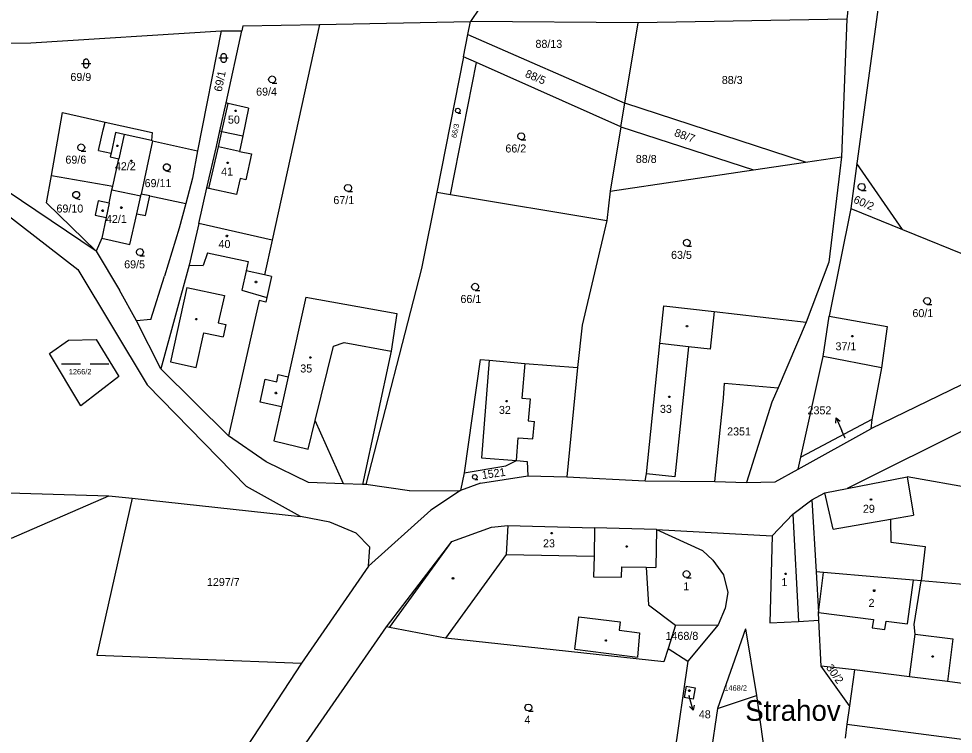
# Model space of a CAD drawing. Extents: x -852001 to -842497, y -1063614 to -1052182.
# Drawn here: x -850781 to -850582.4, y -1053481.6 to -1053329.6 of the extents above; entities that cross this region are included whole.
import ezdxf

# ---------------------------------------------------------------- set-up
doc = ezdxf.new("R2010")
doc.units = 0
for name, color, linetype in [('Default', 7, 'Continuous'), ('KN_HRANICE', 7, 'Continuous'), ('KN_KULTURY', 7, 'Continuous'), ('KN_PARCELY', 7, 'Continuous'), ('KN_SLUCKY', 7, 'Continuous')]:
    doc.layers.add(name, color=color, linetype=linetype)

# ---------------------------------------------------------------- blocks, each defined once
blk = doc.blocks.new('304')
at = {"layer": 'Default'}
blk.add_lwpolyline([(0, 0), (-0.38, 0.1), (-0.65, 0.37), (-0.75, 0.74), (-0.65, 1.11), (-0.38, 1.38), (-0.01, 1.48), (0.36, 1.38), (0.63, 1.11), (0.73, 0.73), (0.63, 0.35), (0.36, 0.08), (-0.02, -0.02), (0.98, -0.02)], dxfattribs=at)
blk = doc.blocks.new('316')
at = {"layer": 'Default'}
for points in [[(-1, 1), (0.27, 1), (1, 1)], [(-0.5, 1.5), (-0.4, 1.79), (-0.15, 1.97), (0.16, 1.97), (0.41, 1.79), (0.51, 1.5), (0.51, 0.5), (0.41, 0.21), (0.16, 0.03), (-0.15, 0.03), (-0.4, 0.21), (-0.5, 0.5), (-0.5, 1.5)]]:
    blk.add_lwpolyline(points, dxfattribs=at)
blk = doc.blocks.new('803')
at = {"layer": 'Default'}
for p, q in [((-7.5, 0), (-1.5, 0)), ((1.5, 0), (7.5, 0))]:
    blk.add_line(p, q, dxfattribs=at)
blk = doc.blocks.new('10292')
at = {"layer": 'Default'}
blk.add_line((0, 3), (0, 0), dxfattribs=at)
blk.add_lwpolyline([(-0.5, 2), (0, 3), (0.5, 2)], dxfattribs=at)
blk = doc.blocks.new('402')
at = {"layer": 'Default'}
blk.add_lwpolyline([(0.09, 0.15), (0.18, 0), (0.09, -0.15), (-0.09, -0.15), (-0.18, 0), (-0.09, 0.15), (0.09, 0.15)], dxfattribs=at)

msp = doc.modelspace()

# ---------------------------------------------------------------- linework, layer by layer
at = {"layer": 'KN_HRANICE'}
for p, q in [((-850601.94, -1053301.5), (-850605.07, -1053329.74)), ((-850595.22, -1053304.04), (-850602.92, -1053360.4)), ((-850683.07, -1053327.37), (-850685.02, -1053330.25)), ((-850717.05, -1053330.88), (-850685.02, -1053330.25)), ((-850685.56, -1053333), (-850685.02, -1053330.25)), ((-850649.35, -1053330.52), (-850685.02, -1053330.25)), ((-850652.19, -1053347.57), (-850649.35, -1053330.52)), ((-850605.07, -1053329.74), (-850649.35, -1053330.52)), ((-850605.07, -1053329.74), (-850606.19, -1053358.98)), ((-850778.4, -1053334.78), (-850737.94, -1053332.24)), ((-850737.94, -1053332.24), (-850742.99, -1053357.7)), ((-850737.94, -1053332.24), (-850733.55, -1053332.18)), ((-850736.86, -1053347.53), (-850733.55, -1053332.18)), ((-850733.34, -1053331.11), (-850733.55, -1053332.18)), ((-850733.34, -1053331.11), (-850717.05, -1053330.88)), ((-850717.05, -1053330.88), (-850727.14, -1053376.69)), ((-850686.5, -1053337.71), (-850685.56, -1053333)), ((-850685.56, -1053333), (-850652.19, -1053347.57)), ((-850815.48, -1053335.08), (-850778.4, -1053334.78)), ((-850686.5, -1053337.71), (-850692.17, -1053366.45)), ((-850683.69, -1053338.94), (-850686.5, -1053337.71)), ((-850689.22, -1053366.95), (-850683.69, -1053338.94)), ((-850653.03, -1053352.56), (-850683.69, -1053338.94)), ((-850738.2, -1053353.47), (-850736.86, -1053347.53)), ((-850736.47, -1053347.62), (-850736.86, -1053347.53)), ((-850732.12, -1053348.62), (-850736.47, -1053347.62)), ((-850653.03, -1053352.56), (-850652.19, -1053347.57)), ((-850613.8, -1053360.1), (-850652.19, -1053347.57)), ((-850774.01, -1053362.91), (-850771.62, -1053349.55)), ((-850771.62, -1053349.55), (-850762.61, -1053351.58)), ((-850732.12, -1053348.62), (-850733.38, -1053354.52)), ((-850762.99, -1053353.25), (-850762.61, -1053351.58)), ((-850762.61, -1053351.58), (-850752.61, -1053353.83)), ((-850763.97, -1053357.61), (-850762.99, -1053353.25)), ((-850752.61, -1053353.83), (-850752.76, -1053355.52)), ((-850738.94, -1053356.76), (-850738.2, -1053353.47)), ((-850738.2, -1053353.47), (-850737.81, -1053353.56)), ((-850737.81, -1053353.56), (-850733.38, -1053354.52)), ((-850733.38, -1053354.52), (-850734.08, -1053357.8)), ((-850653.03, -1053352.56), (-850655.32, -1053366.23)), ((-850653.03, -1053352.56), (-850624.89, -1053361.75)), ((-850752.51, -1053355.58), (-850754.95, -1053366.89)), ((-850752.51, -1053355.58), (-850752.76, -1053355.52)), ((-850752.51, -1053355.58), (-850742.99, -1053357.7)), ((-850763.97, -1053357.61), (-850761.34, -1053358.18)), ((-850761.34, -1053358.18), (-850761.52, -1053358.99)), ((-850742.99, -1053357.7), (-850744.07, -1053363.49)), ((-850740.97, -1053365.57), (-850738.94, -1053356.76)), ((-850734.08, -1053357.8), (-850731.54, -1053358.34)), ((-850731.54, -1053358.34), (-850732.71, -1053363.82)), ((-850761.52, -1053358.99), (-850759.68, -1053359.39)), ((-850760.97, -1053365.18), (-850759.68, -1053359.39)), ((-850624.89, -1053361.75), (-850613.8, -1053360.1)), ((-850613.8, -1053360.1), (-850606.19, -1053358.98)), ((-850606.19, -1053358.98), (-850606.54, -1053361.94)), ((-850602.92, -1053360.4), (-850604.22, -1053369.95)), ((-850593.21, -1053374.4), (-850602.92, -1053360.4)), ((-850655.32, -1053366.23), (-850624.89, -1053361.75)), ((-850606.54, -1053361.94), (-850608.91, -1053381.35)), ((-850775.07, -1053368.7), (-850774.01, -1053362.91)), ((-850774.01, -1053362.91), (-850760.97, -1053365.18)), ((-850744.07, -1053363.49), (-850745.43, -1053368.86)), ((-850733.94, -1053363.56), (-850734.66, -1053366.93)), ((-850732.71, -1053363.82), (-850733.94, -1053363.56)), ((-850764.51, -1053379), (-850783.59, -1053366.1)), ((-850761.73, -1053368.82), (-850761.14, -1053365.96)), ((-850761.14, -1053365.96), (-850760.97, -1053365.18)), ((-850761.14, -1053365.96), (-850755.03, -1053367.28)), ((-850742.71, -1053373.12), (-850740.97, -1053365.57)), ((-850740.58, -1053365.66), (-850740.97, -1053365.57)), ((-850734.66, -1053366.93), (-850740.58, -1053365.66)), ((-850655.32, -1053366.23), (-850656.06, -1053372.51)), ((-850764.08, -1053368.33), (-850764.71, -1053371.37)), ((-850761.73, -1053368.82), (-850764.08, -1053368.33)), ((-850755.03, -1053367.28), (-850754.95, -1053366.89)), ((-850753.13, -1053367.26), (-850754.95, -1053366.89)), ((-850754.04, -1053371.43), (-850753.13, -1053367.26)), ((-850753.13, -1053367.26), (-850745.43, -1053368.86)), ((-850692.17, -1053366.45), (-850695.38, -1053382.66)), ((-850692.17, -1053366.45), (-850689.22, -1053366.95)), ((-850689.22, -1053366.95), (-850656.06, -1053372.51)), ((-850775.07, -1053368.7), (-850764.51, -1053379)), ((-850745.43, -1053368.86), (-850746.88, -1053374.1)), ((-850604.22, -1053369.95), (-850608.81, -1053392.78)), ((-850604.22, -1053369.95), (-850593.21, -1053374.4)), ((-850783.8, -1053370.9), (-850768.38, -1053382.92)), ((-850764.71, -1053371.37), (-850762.36, -1053371.85)), ((-850762.36, -1053371.85), (-850763.28, -1053376.26)), ((-850757.36, -1053377.59), (-850755.86, -1053371.06)), ((-850755.86, -1053371.06), (-850754.04, -1053371.43)), ((-850746.88, -1053374.1), (-850750, -1053384.28)), ((-850742.71, -1053373.12), (-850744.73, -1053381.99)), ((-850727.14, -1053376.69), (-850742.71, -1053373.12)), ((-850656.06, -1053372.51), (-850661.28, -1053394.73)), ((-850763.28, -1053376.26), (-850764.51, -1053379)), ((-850763.28, -1053376.26), (-850757.36, -1053377.59)), ((-850593.21, -1053374.4), (-850558.84, -1053388.31)), ((-850727.14, -1053376.69), (-850728.76, -1053384.05)), ((-850764.51, -1053379), (-850759.56, -1053387.26)), ((-850744.73, -1053381.99), (-850750.73, -1053404.02)), ((-850608.91, -1053381.35), (-850613.67, -1053394.11)), ((-850768.38, -1053382.92), (-850753.68, -1053407.41)), ((-850752.92, -1053393.49), (-850750, -1053384.28)), ((-850727.29, -1053384.37), (-850728.76, -1053384.05)), ((-850695.38, -1053382.66), (-850707.19, -1053428.56)), ((-850727.29, -1053384.37), (-850728.26, -1053388.82)), ((-850755.92, -1053393.81), (-850759.56, -1053387.26)), ((-850729.91, -1053389.48), (-850736.41, -1053418.2)), ((-850728.47, -1053389.8), (-850729.91, -1053389.48)), ((-850728.26, -1053388.82), (-850728.47, -1053389.8)), ((-850719.96, -1053388.76), (-850723.72, -1053405.65)), ((-850719.96, -1053388.76), (-850700.61, -1053392.2)), ((-850700.61, -1053392.2), (-850701.86, -1053400.23)), ((-850644.8, -1053398.62), (-850643.92, -1053390.61)), ((-850643.92, -1053390.61), (-850633.21, -1053391.79)), ((-850633.21, -1053391.79), (-850613.67, -1053394.11)), ((-850752.92, -1053393.49), (-850755.92, -1053393.81)), ((-850750.73, -1053404.02), (-850755.92, -1053393.81)), ((-850613.67, -1053394.11), (-850619.67, -1053408.02)), ((-850610.11, -1053401.34), (-850608.81, -1053392.78)), ((-850608.81, -1053392.78), (-850596.48, -1053395.02)), ((-850661.28, -1053394.73), (-850662.28, -1053403.7)), ((-850596.48, -1053395.02), (-850597.72, -1053403.77)), ((-850774.4, -1053400.72), (-850770.36, -1053397.87)), ((-850770.36, -1053397.87), (-850764.52, -1053397.77)), ((-850764.52, -1053397.77), (-850759.66, -1053405.62)), ((-850647.64, -1053426.28), (-850644.8, -1053398.62)), ((-850767.78, -1053411.85), (-850774.4, -1053400.72)), ((-850701.86, -1053400.23), (-850707.94, -1053428.53)), ((-850682.94, -1053401.97), (-850686.34, -1053426.05)), ((-850682.94, -1053401.97), (-850680.99, -1053402.15)), ((-850680.99, -1053402.15), (-850673.43, -1053402.82)), ((-850614.83, -1053422.71), (-850610.11, -1053401.34)), ((-850736.41, -1053418.2), (-850750.73, -1053404.02)), ((-850673.43, -1053402.82), (-850662.28, -1053403.7)), ((-850662.28, -1053403.7), (-850664.55, -1053426.95)), ((-850597.72, -1053403.77), (-850599.75, -1053414.73)), ((-850759.66, -1053405.62), (-850767.78, -1053411.85)), ((-850726.16, -1053406.74), (-850725.82, -1053405.18)), ((-850725.82, -1053405.18), (-850723.72, -1053405.65)), ((-850732.58, -1053428.94), (-850753.68, -1053407.41)), ((-850729.69, -1053411.08), (-850728.61, -1053406.2)), ((-850728.61, -1053406.2), (-850726.16, -1053406.74)), ((-850631.28, -1053410.23), (-850631.01, -1053407.05)), ((-850631.01, -1053407.05), (-850619.67, -1053408.02)), ((-850619.67, -1053408.02), (-850621, -1053411.06)), ((-850580.7, -1053407.38), (-850599.94, -1053416.73)), ((-850725.15, -1053412.09), (-850729.69, -1053411.08)), ((-850725.15, -1053412.09), (-850726.75, -1053419.27)), ((-850633.09, -1053427.94), (-850631.28, -1053410.23)), ((-850621, -1053411.06), (-850626.39, -1053428.15)), ((-850719.44, -1053421.05), (-850717.98, -1053414.96)), ((-850712, -1053428.38), (-850717.98, -1053414.96)), ((-850599.75, -1053414.73), (-850614.83, -1053422.71)), ((-850574.57, -1053414.22), (-850604.96, -1053429.4)), ((-850599.75, -1053414.73), (-850599.94, -1053416.73)), ((-850615.4, -1053425.29), (-850599.94, -1053416.73)), ((-850728.38, -1053423.75), (-850736.41, -1053418.2)), ((-850726.75, -1053419.27), (-850719.44, -1053421.05)), ((-850719.41, -1053428.11), (-850728.38, -1053423.75)), ((-850677.49, -1053424.55), (-850675.24, -1053423.48)), ((-850675.24, -1053423.48), (-850672.94, -1053423.65)), ((-850672.94, -1053423.65), (-850672.81, -1053426.68)), ((-850615.4, -1053425.29), (-850614.83, -1053422.71)), ((-850686.34, -1053426.05), (-850677.49, -1053424.55)), ((-850620.26, -1053427.98), (-850615.4, -1053425.29)), ((-850686.34, -1053426.05), (-850687.09, -1053429.83)), ((-850682.84, -1053428.25), (-850672.81, -1053426.68)), ((-850672.81, -1053426.68), (-850664.55, -1053426.95)), ((-850664.55, -1053426.95), (-850647.86, -1053427.79)), ((-850647.86, -1053427.79), (-850647.64, -1053426.28)), ((-850647.86, -1053427.79), (-850633.09, -1053427.94)), ((-850633.09, -1053427.94), (-850626.39, -1053428.15)), ((-850626.39, -1053428.15), (-850620.26, -1053427.98)), ((-850604.96, -1053429.4), (-850592.25, -1053426.9)), ((-850592.25, -1053426.9), (-850590.88, -1053435.07)), ((-850572.57, -1053430.44), (-850592.25, -1053426.9)), ((-850800.29, -1053429.81), (-850761.82, -1053430.94)), ((-850721.08, -1053435.35), (-850732.58, -1053428.94)), ((-850712, -1053428.38), (-850719.41, -1053428.11)), ((-850707.94, -1053428.53), (-850712, -1053428.38)), ((-850707.19, -1053428.56), (-850707.94, -1053428.53)), ((-850697.93, -1053429.89), (-850707.19, -1053428.56)), ((-850697.93, -1053429.89), (-850687.09, -1053429.83)), ((-850687.09, -1053429.83), (-850693.44, -1053434)), ((-850682.84, -1053428.25), (-850687.09, -1053429.83)), ((-850609.72, -1053430.34), (-850604.96, -1053429.4)), ((-850782.51, -1053439.96), (-850761.82, -1053430.94)), ((-850756.84, -1053431.48), (-850764.38, -1053464.76)), ((-850761.82, -1053430.94), (-850756.84, -1053431.48)), ((-850756.84, -1053431.48), (-850721.08, -1053435.35)), ((-850616.53, -1053434.88), (-850612.5, -1053431.79)), ((-850612.5, -1053431.79), (-850609.72, -1053430.34)), ((-850612.5, -1053431.79), (-850611.58, -1053447.13)), ((-850714.88, -1053436.58), (-850721.08, -1053435.35)), ((-850693.44, -1053434), (-850706.66, -1053445.91)), ((-850620.91, -1053439.48), (-850616.53, -1053434.88)), ((-850595.77, -1053435.91), (-850590.88, -1053435.07)), ((-850595.77, -1053435.91), (-850595.7, -1053440.8)), ((-850709.27, -1053438.86), (-850714.88, -1053436.58)), ((-850688.95, -1053440.66), (-850680.52, -1053437.6)), ((-850680.52, -1053437.6), (-850677.05, -1053437.23)), ((-850677.05, -1053437.23), (-850658.62, -1053437.73)), ((-850645.45, -1053438.08), (-850658.62, -1053437.73)), ((-850706.34, -1053441.84), (-850709.27, -1053438.86)), ((-850645.45, -1053438.08), (-850645.62, -1053446.16)), ((-850645.45, -1053438.08), (-850620.91, -1053439.48)), ((-850645.45, -1053438.08), (-850635.69, -1053442.58)), ((-850620.91, -1053439.48), (-850621.44, -1053457.94)), ((-850706.66, -1053445.91), (-850706.34, -1053441.84)), ((-850702.85, -1053458.77), (-850688.95, -1053440.66)), ((-850595.7, -1053440.8), (-850588.42, -1053441.72)), ((-850588.42, -1053441.72), (-850589.27, -1053449.03)), ((-850635.69, -1053442.58), (-850633.51, -1053444.61)), ((-850633.51, -1053444.61), (-850631.24, -1053447.76)), ((-850706.66, -1053445.91), (-850720.89, -1053466.48)), ((-850647.67, -1053446.12), (-850645.62, -1053446.16)), ((-850647.67, -1053446.12), (-850647.18, -1053454.08)), ((-850631.24, -1053447.76), (-850630.36, -1053451.52)), ((-850611.58, -1053447.13), (-850611.07, -1053455.75)), ((-850609.98, -1053447.27), (-850611.58, -1053447.13)), ((-850598.49, -1053448.24), (-850609.98, -1053447.27)), ((-850590.92, -1053448.89), (-850598.49, -1053448.24)), ((-850589.27, -1053449.03), (-850590.92, -1053448.89)), ((-850590.78, -1053458.28), (-850589.27, -1053449.03)), ((-850549.87, -1053452.39), (-850589.27, -1053449.03)), ((-850630.36, -1053451.52), (-850630.87, -1053454.82)), ((-850647.18, -1053454.08), (-850641.47, -1053458.44)), ((-850630.87, -1053454.82), (-850632.36, -1053458.32)), ((-850610.99, -1053457.38), (-850611.07, -1053455.75)), ((-850621.44, -1053457.94), (-850615.31, -1053457.61)), ((-850615.31, -1053457.61), (-850610.99, -1053457.38)), ((-850610.48, -1053467.11), (-850610.99, -1053457.38)), ((-850725.03, -1053490.78), (-850702.85, -1053458.77)), ((-850702.16, -1053458.9), (-850702.85, -1053458.77)), ((-850690.27, -1053461.21), (-850702.16, -1053458.9)), ((-850641.47, -1053458.44), (-850643.01, -1053463.36)), ((-850641.47, -1053458.44), (-850632.36, -1053458.32)), ((-850632.36, -1053458.32), (-850638.85, -1053466.06)), ((-850626.55, -1053459.18), (-850632.5, -1053476.14)), ((-850626.55, -1053459.18), (-850624.21, -1053473.39)), ((-850590.54, -1053460.32), (-850590.78, -1053458.28)), ((-850643.91, -1053466.23), (-850690.27, -1053461.21)), ((-850590.54, -1053460.32), (-850582.52, -1053461.36)), ((-850582.52, -1053461.36), (-850583.69, -1053470.39)), ((-850643.01, -1053463.36), (-850643.91, -1053466.23)), ((-850643.01, -1053463.36), (-850638.85, -1053466.06)), ((-850764.38, -1053464.76), (-850720.89, -1053466.48)), ((-850720.89, -1053466.48), (-850743, -1053500.2)), ((-850638.85, -1053466.06), (-850642.9, -1053493.99)), ((-850604.51, -1053475.57), (-850610.48, -1053467.11)), ((-850603.43, -1053467.94), (-850610.48, -1053467.11)), ((-850603.43, -1053467.94), (-850604.51, -1053475.57)), ((-850591.71, -1053469.37), (-850603.43, -1053467.94)), ((-850583.69, -1053470.39), (-850591.71, -1053469.37)), ((-850639.16, -1053471.38), (-850639.58, -1053473.8)), ((-850639.16, -1053471.38), (-850637.24, -1053471.72)), ((-850554.48, -1053474.15), (-850583.69, -1053470.39)), ((-850637.24, -1053471.72), (-850637.66, -1053474.13)), ((-850632.5, -1053476.14), (-850624.21, -1053473.39)), ((-850624.21, -1053473.39), (-850617.15, -1053524.78)), ((-850637.66, -1053474.13), (-850639.58, -1053473.8)), ((-850604.51, -1053475.57), (-850605.06, -1053479.44)), ((-850632.5, -1053476.14), (-850640.52, -1053528.25)), ((-850605.06, -1053479.44), (-850605.41, -1053482.4)), ((-850605.06, -1053479.44), (-850571.78, -1053483.77))]:
    msp.add_line(p, q, dxfattribs=at)
at = {"layer": 'KN_PARCELY'}
for p, q in [((-850605.41, -1053418.73), (-850606.12, -1053417.12)), ((-850638.6, -1053473.28), (-850638.51, -1053473.6))]:
    msp.add_line(p, q, dxfattribs=at)
at = {"layer": 'KN_SLUCKY'}
for p, q in [((-850737.81, -1053353.56), (-850736.47, -1053347.62)), ((-850760.4, -1053353.83), (-850761.34, -1053358.18)), ((-850758.56, -1053354.23), (-850760.4, -1053353.83)), ((-850758.56, -1053354.23), (-850759.68, -1053359.39)), ((-850752.76, -1053355.52), (-850758.56, -1053354.23)), ((-850738.55, -1053356.85), (-850737.81, -1053353.56)), ((-850740.58, -1053365.66), (-850738.55, -1053356.85)), ((-850734.08, -1053357.8), (-850738.55, -1053356.85)), ((-850755.86, -1053371.06), (-850755.03, -1053367.28)), ((-850761.73, -1053368.82), (-850762.36, -1053371.85)), ((-850740.86, -1053379.33), (-850741.78, -1053382.03)), ((-850740.86, -1053379.33), (-850732.23, -1053381.21)), ((-850744.73, -1053381.99), (-850741.78, -1053382.03)), ((-850732.23, -1053381.21), (-850732.66, -1053383.2)), ((-850732.66, -1053383.2), (-850733.55, -1053387.28)), ((-850728.76, -1053384.05), (-850732.66, -1053383.2)), ((-850745.21, -1053386.71), (-850748.7, -1053402.5)), ((-850745.21, -1053386.71), (-850737.24, -1053388.44)), ((-850733.55, -1053387.28), (-850728.26, -1053388.82)), ((-850737.24, -1053388.44), (-850738.57, -1053394.19)), ((-850633.21, -1053391.79), (-850634.1, -1053399.81)), ((-850738.57, -1053394.19), (-850736.94, -1053394.57)), ((-850736.94, -1053394.57), (-850737.55, -1053397.22)), ((-850743.26, -1053403.71), (-850741.63, -1053396.36)), ((-850741.63, -1053396.36), (-850739.2, -1053396.84)), ((-850739.2, -1053396.84), (-850737.55, -1053397.22)), ((-850717.98, -1053414.96), (-850714.06, -1053399.19)), ((-850714.06, -1053399.19), (-850711.85, -1053398.4)), ((-850711.85, -1053398.4), (-850701.86, -1053400.23)), ((-850638.67, -1053399.32), (-850644.8, -1053398.62)), ((-850638.67, -1053399.32), (-850641.6, -1053426.95)), ((-850634.1, -1053399.81), (-850638.67, -1053399.32)), ((-850680.99, -1053402.15), (-850682.67, -1053422.88)), ((-850597.72, -1053403.77), (-850610.11, -1053401.34)), ((-850748.7, -1053402.5), (-850743.26, -1053403.71)), ((-850673.43, -1053402.82), (-850674.07, -1053410.23)), ((-850723.72, -1053405.65), (-850725.15, -1053412.09)), ((-850674.07, -1053410.23), (-850672.33, -1053410.38)), ((-850672.33, -1053410.38), (-850672.74, -1053415.05)), ((-850672.74, -1053415.05), (-850671.4, -1053415.17)), ((-850671.72, -1053418.85), (-850671.4, -1053415.17)), ((-850675.24, -1053423.48), (-850674.85, -1053418.65)), ((-850674.85, -1053418.65), (-850671.72, -1053418.85)), ((-850682.67, -1053422.88), (-850675.24, -1053423.48)), ((-850641.6, -1053426.95), (-850647.64, -1053426.28)), ((-850607.95, -1053438), (-850609.72, -1053430.34)), ((-850616.53, -1053434.88), (-850615.31, -1053457.61)), ((-850607.95, -1053438), (-850595.77, -1053435.91)), ((-850677.05, -1053437.23), (-850677.39, -1053443.4)), ((-850658.62, -1053437.73), (-850658.75, -1053443.79)), ((-850702.16, -1053458.9), (-850688.95, -1053440.66)), ((-850677.39, -1053443.4), (-850690.27, -1053461.21)), ((-850677.39, -1053443.4), (-850658.75, -1053443.79)), ((-850658.75, -1053443.79), (-850658.84, -1053448.14)), ((-850652.91, -1053448.26), (-850652.86, -1053446.01)), ((-850652.86, -1053446.01), (-850647.67, -1053446.12)), ((-850611.07, -1053455.75), (-850609.98, -1053447.27)), ((-850658.84, -1053448.14), (-850652.91, -1053448.26)), ((-850592.14, -1053458.14), (-850590.92, -1053448.89)), ((-850611.07, -1053455.75), (-850599.4, -1053457.2)), ((-850662.83, -1053463.54), (-850661.97, -1053456.66)), ((-850661.97, -1053456.66), (-850653.22, -1053457.69)), ((-850653.22, -1053457.69), (-850653.42, -1053459.46)), ((-850599.4, -1053457.2), (-850599.64, -1053458.96)), ((-850596.96, -1053459.31), (-850596.73, -1053457.54)), ((-850596.73, -1053457.54), (-850592.14, -1053458.14)), ((-850653.42, -1053459.46), (-850649.08, -1053460.02)), ((-850599.64, -1053458.96), (-850596.96, -1053459.31)), ((-850649.08, -1053460.02), (-850649.51, -1053465.22)), ((-850591.71, -1053469.37), (-850590.54, -1053460.32)), ((-850662.83, -1053463.54), (-850649.51, -1053465.22))]:
    msp.add_line(p, q, dxfattribs=at)

# ---------------------------------------------------------------- block references
at = {"layer": 'KN_KULTURY'}
for name, p in [('316', (-850766.65, -1053340.15)), ('316', (-850737.43, -1053338.97)), ('304', (-850727.12, -1053343.27)), ('402', (-850734.89, -1053349.21)), ('304', (-850674.22, -1053355.34)), ('304', (-850767.67, -1053357.71)), ('402', (-850759.98, -1053356.64)), ('402', (-850757.04, -1053359.79)), ('402', (-850736.58, -1053360.24)), ('304', (-850711, -1053366.3)), ('304', (-850601.9, -1053366.1)), ('402', (-850763.15, -1053370.39)), ('402', (-850759.13, -1053369.76)), ('402', (-850736.74, -1053375.78)), ('304', (-850639.03, -1053377.94)), ('304', (-850755.19, -1053379.94)), ('402', (-850730.54, -1053385.54)), ('304', (-850684, -1053387.3)), ('304', (-850588, -1053390.3)), ('402', (-850743.25, -1053393.45)), ('402', (-850639.02, -1053394.93)), ('402', (-850603.89, -1053397.04)), ('402', (-850718.98, -1053401.6)), ('402', (-850726.33, -1053409.11)), ('402', (-850642.75, -1053409.95)), ('402', (-850677.33, -1053410.86)), ('402', (-850599.91, -1053431.74)), ('402', (-850667.76, -1053438.91)), ('402', (-850651.8, -1053441.74)), ('304', (-850639.09, -1053448.32)), ('402', (-850618.07, -1053447.5)), ('402', (-850688.69, -1053448.47)), ('402', (-850599.25, -1053451.1)), ('402', (-850656.24, -1053461.68)), ('402', (-850586.83, -1053465.09)), ('402', (-850638.51, -1053472.33)), ('304', (-850672.68, -1053476.65))]:
    msp.add_blockref(name, p, dxfattribs=at)
at = {"layer": 'KN_KULTURY', "xscale": 0.67, "yscale": 0.67}
for name, p in [('304', (-850687.68, -1053349.65)), ('803', (-850766.81, -1053402.95)), ('304', (-850684.08, -1053427.44))]:
    msp.add_blockref(name, p, dxfattribs=at)
at = {"layer": 'KN_KULTURY', "rotation": -13.589717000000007}
for p in [(-850749.67, -1053361.91), (-850749.67, -1053361.91), (-850768.9, -1053367.74), (-850768.9, -1053367.74)]:
    msp.add_blockref('304', p, dxfattribs=at)
at = {"layer": 'KN_PARCELY'}
for p, rotation in [((-850606.12, -1053417.12), 23.663157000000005), ((-850638.51, -1053473.6), -164.90787100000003)]:
    msp.add_blockref('10292', p, dxfattribs=dict(at, rotation=rotation))

# ---------------------------------------------------------------- texts
for s, height, p in [('88/13', 1.7, (-850671.19, -1053335.82)), ('69/9', 1.7, (-850769.97, -1053342.85)), ('88/3', 1.7, (-850631.61, -1053343.49)), ('69/4', 1.7, (-850730.52, -1053345.97)), ('50', 1.7, (-850736.51, -1053351.91)), ('66/2', 1.7, (-850677.58, -1053358.04)), ('88/8', 1.7, (-850649.88, -1053360.26)), ('69/6', 1.7, (-850771.03, -1053360.41)), ('42/2', 1.7, (-850760.52, -1053361.81)), ('41', 1.7, (-850737.96, -1053362.94)), ('69/11', 1.7, (-850754.21, -1053365.4)), ('67/1', 1.7, (-850714.12, -1053369)), ('69/10', 1.7, (-850772.93, -1053370.79)), ('42/1', 1.7, (-850762.42, -1053373.01)), ('40', 1.7, (-850738.51, -1053378.33)), ('63/5', 1.7, (-850642.39, -1053380.64)), ('69/5', 1.7, (-850758.55, -1053382.64)), ('66/1', 1.7, (-850687.12, -1053390)), ('60/1', 1.7, (-850591.12, -1053393)), ('37/1', 1.7, (-850607.46, -1053400.05)), ('1266/2', 1.14, (-850770.32, -1053405.16)), ('35', 1.7, (-850721.14, -1053404.76)), ('32', 1.7, (-850678.95, -1053413.56)), ('33', 1.7, (-850644.75, -1053413.34)), ('2352', 1.7, (-850613.4, -1053413.65)), ('2351', 1.7, (-850630.48, -1053418.13)), ('29', 1.7, (-850601.63, -1053434.55)), ('23', 1.7, (-850669.59, -1053441.89)), ('1297/7', 1.7, (-850740.97, -1053450.1)), ('1', 1.7, (-850639.78, -1053451.02)), ('1', 1.7, (-850618.94, -1053450.13)), ('2', 1.7, (-850600.44, -1053454.54)), ('1468/8', 1.7, (-850643.56, -1053461.54)), ('1468/2', 1.14, (-850631.08, -1053472.34)), ('48', 0.1, (-850638.7, -1053473.28)), ('Strahov', 4.4, (-850626.63, -1053478.74)), ('48', 1.7, (-850636.49, -1053478.2)), ('4', 1.7, (-850673.53, -1053479.35))]:
    msp.add_text(s, height=height, dxfattribs=at).set_placement(p)
for s, height, rotation, p in [('88/5', 1.7, 337.128, (-850673.54, -1053341.94)), ('69/1', 1.7, 78.495, (-850737.84, -1053345.24)), ('66/3', 1.14, 78.266, (-850687.98, -1053355.04)), ('88/7', 1.7, 340.05, (-850641.85, -1053354.5)), ('60/2', 1.7, 336.498, (-850603.8, -1053368.64)), ('2352', 0.1, 26.356, (-850605.58, -1053418.81)), ('1521', 1.7, 8.079, (-850682.46, -1053427.4)), ('30/2', 1.7, 305.157, (-850609.56, -1053467.45))]:
    msp.add_text(s, height=height, rotation=rotation, dxfattribs=at).set_placement(p)

doc.saveas('drawing.dxf')
